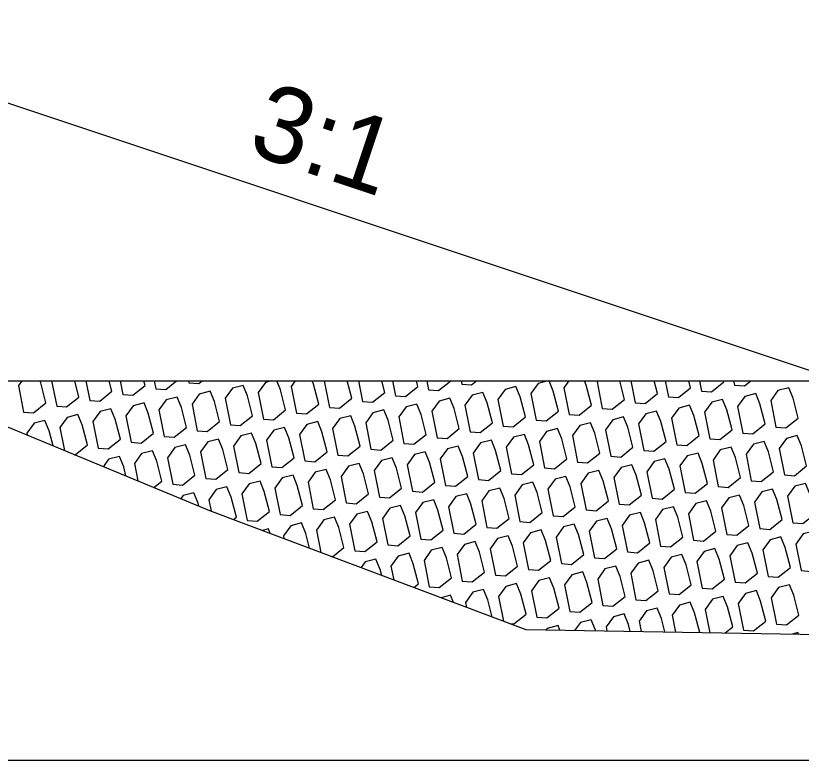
# Model space of a CAD drawing. Extents: x -26 to 203, y -10 to 20020.
# Drawn here: x 122.84 to 131.13, y 17500 to 17507.85 of the extents above; entities that cross this region are included whole.
import ezdxf

# ---------------------------------------------------------------- set-up
doc = ezdxf.new("R2010")
doc.units = 0
for name, color, linetype in [('Exist Cross Section Cell', 7, 'Continuous'), ('Exist XS Ground Line', 7, 'Continuous'), ('Old_Level_1', 7, 'Continuous'), ('Prop CMT Rip Rap Class II', 7, 'Continuous'), ('Prop CMT Slope Grass', 7, 'Continuous'), ('Prop XS Side Slope Text', 7, 'Continuous')]:
    doc.layers.add(name, color=color, linetype=linetype)

msp = doc.modelspace()

# ---------------------------------------------------------------- linework, layer by layer
at = {"layer": 'Exist Cross Section Cell'}
msp.add_line((100, 17500), (200, 17500), dxfattribs=at)
at = {"layer": 'Exist XS Ground Line'}
for p, q in [((122.4332, 17503.6477), (124.8872, 17502.6334)), ((124.8872, 17502.6334), (128.2219, 17501.3773)), ((128.2219, 17501.3773), (137.4014, 17501.2258))]:
    msp.add_line(p, q, dxfattribs=at)
at = {"layer": 'Old_Level_1'}
for p, q in [((123.2212, 17504), (123.2742, 17503.7332)), ((123.582, 17504), (123.6228, 17503.7947)), ((123.9428, 17504), (123.9713, 17503.8562)), ((124.3036, 17504), (124.3199, 17503.9176)), ((124.6644, 17504), (124.6685, 17503.9791)), ((126.0964, 17504), (126.1518, 17503.7209)), ((126.4572, 17504), (126.5004, 17503.7824)), ((126.818, 17504), (126.849, 17503.8438)), ((127.1788, 17504), (127.1976, 17503.9053)), ((127.5396, 17504), (127.5462, 17503.9668)), ((129.3324, 17504), (129.3781, 17503.77)), ((129.6932, 17504), (129.7267, 17503.8315)), ((130.054, 17504), (130.0753, 17503.893)), ((130.4148, 17504), (130.4238, 17503.9544))]:
    msp.add_line(p, q, dxfattribs=at)
for points in [[(122.9049, 17504), (122.8699, 17503.9518), (122.9256, 17503.6718)], [(122.9256, 17503.6718), (123.0308, 17503.6641), (123.1604, 17503.7673), (123.1059, 17503.9779), (123.0968, 17504)], [(123.2742, 17503.7332), (123.3794, 17503.7256), (123.509, 17503.8288), (123.4647, 17504)], [(123.6228, 17503.7947), (123.728, 17503.7871), (123.8576, 17503.8903), (123.8292, 17504)], [(123.9713, 17503.8562), (124.0766, 17503.8485), (124.2062, 17503.9517), (124.1937, 17504)], [(124.3199, 17503.9176), (124.4252, 17503.91), (124.5382, 17504)], [(124.6685, 17503.9791), (124.7738, 17503.9715), (124.8096, 17504)], [(125.106, 17503.5365), (125.2113, 17503.5289), (125.3408, 17503.6321), (125.2864, 17503.8426), (125.2412, 17503.9523), (125.1275, 17503.9229), (125.0504, 17503.8165), (125.106, 17503.5365)], [(125.5364, 17504), (125.4761, 17503.9844), (125.399, 17503.878), (125.4546, 17503.598)], [(125.4546, 17503.598), (125.5599, 17503.5903), (125.6894, 17503.6935), (125.635, 17503.9041), (125.5955, 17504)], [(125.7915, 17504), (125.7476, 17503.9394), (125.8032, 17503.6594)], [(125.8032, 17503.6594), (125.9085, 17503.6518), (126.038, 17503.755), (125.9836, 17503.9656), (125.9694, 17504)], [(126.1518, 17503.7209), (126.2571, 17503.7133), (126.3866, 17503.8165), (126.3392, 17504)], [(126.5004, 17503.7824), (126.6057, 17503.7747), (126.7352, 17503.8779), (126.7036, 17504)], [(126.849, 17503.8438), (126.9543, 17503.8362), (127.0838, 17503.9394), (127.0681, 17504)], [(127.1976, 17503.9053), (127.3029, 17503.8977), (127.4313, 17504)], [(127.5462, 17503.9668), (127.6515, 17503.9591), (127.7028, 17504)], [(128.4618, 17504), (128.3537, 17503.9721), (128.2767, 17503.8656), (128.3323, 17503.5856)], [(128.3323, 17503.5856), (128.4375, 17503.578), (128.5671, 17503.6812), (128.5126, 17503.8918), (128.4681, 17504)], [(128.678, 17504), (128.6253, 17503.9271), (128.6809, 17503.6471)], [(128.6809, 17503.6471), (128.7861, 17503.6395), (128.9157, 17503.7427), (128.8612, 17503.9532), (128.842, 17504)], [(128.9821, 17504), (128.9739, 17503.9886), (129.0295, 17503.7086)], [(129.0295, 17503.7086), (129.1347, 17503.7009), (129.2643, 17503.8041), (129.2136, 17504)], [(129.3781, 17503.77), (129.4833, 17503.7624), (129.6129, 17503.8656), (129.5781, 17504)], [(129.7267, 17503.8315), (129.8319, 17503.8239), (129.9615, 17503.9271), (129.9426, 17504)], [(130.0753, 17503.893), (130.1805, 17503.8853), (130.3101, 17503.9885), (130.3071, 17504)], [(130.4238, 17503.9544), (130.5291, 17503.9468), (130.5959, 17504)], [(124.7574, 17503.475), (124.8627, 17503.4674), (124.9922, 17503.5706), (124.9378, 17503.7812), (124.8926, 17503.8909), (124.7789, 17503.8615), (124.7018, 17503.755), (124.7574, 17503.475)], [(127.6351, 17503.4627), (127.7403, 17503.4551), (127.8699, 17503.5583), (127.8154, 17503.7688), (127.7703, 17503.8785), (127.6565, 17503.8491), (127.5795, 17503.7427), (127.6351, 17503.4627)], [(127.9837, 17503.5242), (128.0889, 17503.5165), (128.2185, 17503.6197), (128.164, 17503.8303), (128.1189, 17503.94), (128.0051, 17503.9106), (127.9281, 17503.8042), (127.9837, 17503.5242)], [(124.4088, 17503.4136), (124.5141, 17503.4059), (124.6436, 17503.5091), (124.5892, 17503.7197), (124.544, 17503.8294), (124.4303, 17503.8), (124.3532, 17503.6936), (124.4088, 17503.4136)], [(123.7116, 17503.2906), (123.8169, 17503.283), (123.9464, 17503.3862), (123.892, 17503.5968), (123.8468, 17503.7065), (123.7331, 17503.6771), (123.656, 17503.5706), (123.7116, 17503.2906)], [(124.0602, 17503.3521), (124.1655, 17503.3445), (124.295, 17503.4477), (124.2406, 17503.6582), (124.1954, 17503.7679), (124.0817, 17503.7385), (124.0046, 17503.6321), (124.0602, 17503.3521)], [(123.4634, 17503.2219), (123.4683, 17503.2215), (123.5978, 17503.3247), (123.5434, 17503.5353), (123.4982, 17503.645), (123.3845, 17503.6156), (123.3074, 17503.5092), (123.3556, 17503.2664)], [(123.2356, 17503.316), (123.1948, 17503.4738), (123.1497, 17503.5835), (123.0359, 17503.5541), (122.9588, 17503.4477), (122.9626, 17503.4289)], [(124.0054, 17502.9979), (123.9809, 17503.0927), (123.9357, 17503.2024), (123.822, 17503.173), (123.7666, 17503.0966)], [(124.2995, 17502.8763), (124.3839, 17502.9436), (124.3295, 17503.1542), (124.2843, 17503.2639), (124.1706, 17503.2345), (124.0935, 17503.128), (124.1295, 17502.9466)], [(125.1397, 17502.5383), (125.17, 17502.5625), (125.1155, 17502.773), (125.0704, 17502.8827), (124.9566, 17502.8533), (124.8796, 17502.7469), (124.9033, 17502.6273)], [(125.2838, 17502.5284), (125.389, 17502.5207), (125.5186, 17502.6239), (125.4641, 17502.8345), (125.419, 17502.9442), (125.3052, 17502.9148), (125.2282, 17502.8084), (125.2838, 17502.5284)], [(124.7752, 17502.6797), (124.7669, 17502.7116), (124.7218, 17502.8213), (124.608, 17502.7919), (124.584, 17502.7587)], [(126.4185, 17502.2087), (126.5237, 17502.2011), (126.6533, 17502.3043), (126.5988, 17502.5148), (126.5537, 17502.6245), (126.4399, 17502.5951), (126.3628, 17502.4887), (126.4185, 17502.2087)], [(126.1825, 17502.1455), (126.3047, 17502.2428), (126.2502, 17502.4534), (126.2051, 17502.5631), (126.0913, 17502.5337), (126.0142, 17502.4272), (126.0611, 17502.1912)], [(125.9419, 17502.2361), (125.9016, 17502.3919), (125.8565, 17502.5016), (125.7427, 17502.4722), (125.6656, 17502.3658), (125.6711, 17502.3381)], [(125.5276, 17502.3922), (125.5079, 17502.4401), (125.4441, 17502.4236)], [(127.2045, 17501.8276), (127.3098, 17501.8199), (127.4393, 17501.9231), (127.3849, 17502.1337), (127.3397, 17502.2434), (127.226, 17502.214), (127.1489, 17502.1076), (127.2045, 17501.8276)], [(126.7036, 17501.9492), (126.6877, 17502.0108), (126.6425, 17502.1205), (126.5288, 17502.0911), (126.4856, 17502.0313)], [(127.0411, 17501.8221), (127.0907, 17501.8617), (127.0363, 17502.0722), (126.9911, 17502.1819), (126.8774, 17502.1525), (126.8003, 17502.0461), (126.8289, 17501.902)], [(128.3392, 17501.5079), (128.4445, 17501.5003), (128.574, 17501.6035), (128.5196, 17501.814), (128.4744, 17501.9237), (128.3606, 17501.8943), (128.2836, 17501.7879), (128.3392, 17501.5079)], [(127.8691, 17501.5102), (127.8224, 17501.6911), (127.7772, 17501.8008), (127.6635, 17501.7714), (127.5864, 17501.665), (127.5968, 17501.6128)], [(128.0498, 17501.4421), (128.0959, 17501.4388), (128.2254, 17501.542), (128.171, 17501.7526), (128.1258, 17501.8623), (128.0121, 17501.8328), (127.935, 17501.7264), (127.9867, 17501.4659)], [(127.4594, 17501.6645), (127.4286, 17501.7393), (127.3291, 17501.7136)], [(130.3254, 17501.3426), (130.4059, 17501.4067), (130.3514, 17501.6173), (130.3063, 17501.727), (130.1925, 17501.6976), (130.1155, 17501.5912), (130.1643, 17501.3452)], [(130.0568, 17501.347), (130.0028, 17501.5558), (129.9577, 17501.6655), (129.8439, 17501.6361), (129.7669, 17501.5297), (129.8023, 17501.3512)], [(129.3247, 17501.3591), (129.3056, 17501.4329), (129.2605, 17501.5426), (129.1467, 17501.5132), (129.0697, 17501.4068), (129.0783, 17501.3632)], [(129.6908, 17501.3531), (129.6542, 17501.4944), (129.6091, 17501.6041), (129.4953, 17501.5746), (129.4183, 17501.4682), (129.4403, 17501.3572)], [(128.9587, 17501.3651), (128.957, 17501.3714), (128.9119, 17501.4811), (128.7981, 17501.4517), (128.7381, 17501.3688)], [(128.5832, 17501.3713), (128.5633, 17501.4197), (128.4495, 17501.3902), (128.4376, 17501.3737)], [(131.099, 17501.3298), (131.0923, 17501.3459), (131.0344, 17501.3309)]]:
    msp.add_lwpolyline(points, dxfattribs=at)
for points in [[(130.5127, 17503.4504), (130.618, 17503.4427), (130.7475, 17503.5459), (130.6931, 17503.7565), (130.6479, 17503.8662), (130.5342, 17503.8368), (130.4571, 17503.7304)], [(130.8613, 17503.5118), (130.9666, 17503.5042), (131.0961, 17503.6074), (131.0417, 17503.818), (130.9965, 17503.9277), (130.8828, 17503.8983), (130.8057, 17503.7918)], [(127.2865, 17503.4012), (127.3917, 17503.3936), (127.5213, 17503.4968), (127.4668, 17503.7074), (127.4217, 17503.8171), (127.3079, 17503.7877), (127.2309, 17503.6812)], [(130.1641, 17503.3889), (130.2694, 17503.3813), (130.3989, 17503.4845), (130.3445, 17503.695), (130.2993, 17503.8047), (130.1856, 17503.7753), (130.1085, 17503.6689)], [(126.5893, 17503.2783), (126.6946, 17503.2707), (126.8241, 17503.3739), (126.7696, 17503.5844), (126.7245, 17503.6941), (126.6107, 17503.6647), (126.5337, 17503.5583)], [(126.9379, 17503.3398), (127.0431, 17503.3321), (127.1727, 17503.4353), (127.1182, 17503.6459), (127.0731, 17503.7556), (126.9593, 17503.7262), (126.8823, 17503.6198)], [(129.8155, 17503.3274), (129.9208, 17503.3198), (130.0503, 17503.423), (129.9959, 17503.6336), (129.9507, 17503.7433), (129.837, 17503.7139), (129.7599, 17503.6074)], [(126.2407, 17503.2168), (126.346, 17503.2092), (126.4755, 17503.3124), (126.421, 17503.523), (126.3759, 17503.6327), (126.2621, 17503.6033), (126.1851, 17503.4968)], [(129.1183, 17503.2045), (129.2236, 17503.1969), (129.3531, 17503.3001), (129.2987, 17503.5106), (129.2536, 17503.6203), (129.1398, 17503.5909), (129.0627, 17503.4845)], [(129.4669, 17503.266), (129.5722, 17503.2583), (129.7017, 17503.3615), (129.6473, 17503.5721), (129.6022, 17503.6818), (129.4884, 17503.6524), (129.4113, 17503.546)], [(125.8921, 17503.1554), (125.9974, 17503.1477), (126.1269, 17503.2509), (126.0725, 17503.4615), (126.0273, 17503.5712), (125.9135, 17503.5418), (125.8365, 17503.4354)], [(128.7697, 17503.143), (128.875, 17503.1354), (129.0045, 17503.2386), (128.9501, 17503.4492), (128.905, 17503.5589), (128.7912, 17503.5295), (128.7141, 17503.423)], [(125.1949, 17503.0324), (125.3002, 17503.0248), (125.4297, 17503.128), (125.3753, 17503.3386), (125.3301, 17503.4483), (125.2164, 17503.4189), (125.1393, 17503.3124)], [(125.5435, 17503.0939), (125.6488, 17503.0863), (125.7783, 17503.1895), (125.7239, 17503.4), (125.6787, 17503.5097), (125.5649, 17503.4803), (125.4879, 17503.3739)], [(128.4212, 17503.0816), (128.5264, 17503.0739), (128.656, 17503.1771), (128.6015, 17503.3877), (128.5564, 17503.4974), (128.4426, 17503.468), (128.3655, 17503.3616)], [(124.8463, 17502.971), (124.9516, 17502.9633), (125.0811, 17503.0665), (125.0267, 17503.2771), (124.9815, 17503.3868), (124.8678, 17503.3574), (124.7907, 17503.251)], [(127.724, 17502.9586), (127.8292, 17502.951), (127.9588, 17503.0542), (127.9043, 17503.2648), (127.8592, 17503.3745), (127.7454, 17503.3451), (127.6683, 17503.2386)], [(128.0726, 17503.0201), (128.1778, 17503.0125), (128.3074, 17503.1157), (128.2529, 17503.3262), (128.2078, 17503.4359), (128.094, 17503.4065), (128.0169, 17503.3001)], [(130.6016, 17502.9463), (130.7069, 17502.9387), (130.8364, 17503.0419), (130.782, 17503.2524), (130.7368, 17503.3621), (130.6231, 17503.3327), (130.546, 17503.2263)], [(130.9502, 17503.0078), (131.0555, 17503.0001), (131.185, 17503.1033), (131.1306, 17503.3139), (131.0854, 17503.4236), (130.9717, 17503.3942), (130.8946, 17503.2878)], [(124.4977, 17502.9095), (124.603, 17502.9019), (124.7325, 17503.0051), (124.6781, 17503.2156), (124.6329, 17503.3253), (124.5192, 17503.2959), (124.4421, 17503.1895)], [(127.3754, 17502.8972), (127.4806, 17502.8895), (127.6102, 17502.9927), (127.5557, 17503.2033), (127.5106, 17503.313), (127.3968, 17503.2836), (127.3198, 17503.1772)], [(130.253, 17502.8848), (130.3583, 17502.8772), (130.4878, 17502.9804), (130.4334, 17503.191), (130.3882, 17503.3007), (130.2745, 17503.2713), (130.1974, 17503.1648)], [(127.0268, 17502.8357), (127.132, 17502.8281), (127.2616, 17502.9313), (127.2071, 17503.1418), (127.162, 17503.2515), (127.0482, 17503.2221), (126.9712, 17503.1157)], [(129.9044, 17502.8234), (130.0097, 17502.8157), (130.1392, 17502.9189), (130.0848, 17503.1295), (130.0396, 17503.2392), (129.9259, 17503.2098), (129.8488, 17503.1034)], [(126.3296, 17502.7128), (126.4348, 17502.7051), (126.5644, 17502.8083), (126.5099, 17503.0189), (126.4648, 17503.1286), (126.351, 17503.0992), (126.274, 17502.9928)], [(126.6782, 17502.7742), (126.7834, 17502.7666), (126.913, 17502.8698), (126.8585, 17503.0804), (126.8134, 17503.1901), (126.6996, 17503.1607), (126.6226, 17503.0542)], [(129.2072, 17502.7004), (129.3125, 17502.6928), (129.442, 17502.796), (129.3876, 17503.0066), (129.3424, 17503.1163), (129.2287, 17503.0869), (129.1516, 17502.9804)], [(129.5558, 17502.7619), (129.6611, 17502.7543), (129.7906, 17502.8575), (129.7362, 17503.068), (129.691, 17503.1777), (129.5773, 17503.1483), (129.5002, 17503.0419)], [(125.981, 17502.6513), (126.0862, 17502.6437), (126.2158, 17502.7469), (126.1613, 17502.9574), (126.1162, 17503.0671), (126.0024, 17503.0377), (125.9254, 17502.9313)], [(128.8586, 17502.639), (128.9639, 17502.6313), (129.0934, 17502.7345), (129.039, 17502.9451), (128.9938, 17503.0548), (128.8801, 17503.0254), (128.803, 17502.919)], [(125.6324, 17502.5898), (125.7376, 17502.5822), (125.8672, 17502.6854), (125.8127, 17502.896), (125.7676, 17503.0057), (125.6538, 17502.9763), (125.5768, 17502.8698)], [(128.51, 17502.5775), (128.6153, 17502.5699), (128.7448, 17502.6731), (128.6904, 17502.8836), (128.6452, 17502.9933), (128.5315, 17502.9639), (128.4544, 17502.8575)], [(127.8128, 17502.4546), (127.9181, 17502.4469), (128.0476, 17502.5501), (127.9932, 17502.7607), (127.9481, 17502.8704), (127.8343, 17502.841), (127.7572, 17502.7346)], [(128.1614, 17502.516), (128.2667, 17502.5084), (128.3962, 17502.6116), (128.3418, 17502.8222), (128.2966, 17502.9319), (128.1829, 17502.9025), (128.1058, 17502.796)], [(131.0391, 17502.5037), (131.1444, 17502.4961), (131.2739, 17502.5993), (131.2194, 17502.8098), (131.1743, 17502.9195), (131.0605, 17502.8901), (130.9835, 17502.7837)], [(127.4642, 17502.3931), (127.5695, 17502.3855), (127.699, 17502.4887), (127.6446, 17502.6992), (127.5995, 17502.8089), (127.4857, 17502.7795), (127.4086, 17502.6731)], [(130.3419, 17502.3808), (130.4472, 17502.3731), (130.5767, 17502.4763), (130.5223, 17502.6869), (130.4771, 17502.7966), (130.3633, 17502.7672), (130.2863, 17502.6608)], [(130.6905, 17502.4422), (130.7958, 17502.4346), (130.9253, 17502.5378), (130.8708, 17502.7484), (130.8257, 17502.8581), (130.7119, 17502.8287), (130.6349, 17502.7222)], [(127.1156, 17502.3316), (127.2209, 17502.324), (127.3504, 17502.4272), (127.296, 17502.6378), (127.2509, 17502.7475), (127.1371, 17502.7181), (127.06, 17502.6116)], [(129.9933, 17502.3193), (130.0986, 17502.3117), (130.2281, 17502.4149), (130.1737, 17502.6254), (130.1285, 17502.7351), (130.0148, 17502.7057), (129.9377, 17502.5993)], [(126.767, 17502.2702), (126.8723, 17502.2625), (127.0019, 17502.3657), (126.9474, 17502.5763), (126.9023, 17502.686), (126.7885, 17502.6566), (126.7114, 17502.5502)], [(129.6447, 17502.2578), (129.75, 17502.2502), (129.8795, 17502.3534), (129.8251, 17502.564), (129.7799, 17502.6737), (129.6662, 17502.6443), (129.5891, 17502.5378)], [(128.9475, 17502.1349), (129.0528, 17502.1273), (129.1823, 17502.2305), (129.1279, 17502.441), (129.0827, 17502.5507), (128.969, 17502.5213), (128.8919, 17502.4149)], [(129.2961, 17502.1964), (129.4014, 17502.1887), (129.5309, 17502.2919), (129.4765, 17502.5025), (129.4313, 17502.6122), (129.3176, 17502.5828), (129.2405, 17502.4764)], [(128.5989, 17502.0734), (128.7042, 17502.0658), (128.8337, 17502.169), (128.7793, 17502.3796), (128.7341, 17502.4893), (128.6204, 17502.4599), (128.5433, 17502.3534)], [(127.9017, 17501.9505), (128.007, 17501.9429), (128.1365, 17502.0461), (128.0821, 17502.2566), (128.0369, 17502.3663), (127.9232, 17502.3369), (127.8461, 17502.2305)], [(128.2503, 17502.012), (128.3556, 17502.0043), (128.4851, 17502.1075), (128.4307, 17502.3181), (128.3855, 17502.4278), (128.2718, 17502.3984), (128.1947, 17502.292)], [(131.128, 17501.9996), (131.2332, 17501.992), (131.3628, 17502.0952), (131.3083, 17502.3058), (131.2632, 17502.4155), (131.1494, 17502.3861), (131.0724, 17502.2796)], [(127.5531, 17501.889), (127.6584, 17501.8814), (127.7879, 17501.9846), (127.7335, 17502.1952), (127.6883, 17502.3049), (127.5746, 17502.2755), (127.4975, 17502.169)], [(130.4308, 17501.8767), (130.536, 17501.8691), (130.6656, 17501.9723), (130.6111, 17502.1828), (130.566, 17502.2925), (130.4522, 17502.2631), (130.3752, 17502.1567)], [(130.7794, 17501.9382), (130.8846, 17501.9305), (131.0142, 17502.0337), (130.9597, 17502.2443), (130.9146, 17502.354), (130.8008, 17502.3246), (130.7238, 17502.2182)], [(130.0822, 17501.8152), (130.1874, 17501.8076), (130.317, 17501.9108), (130.2625, 17502.1214), (130.2174, 17502.2311), (130.1036, 17502.2017), (130.0266, 17502.0952)], [(129.7336, 17501.7538), (129.8388, 17501.7461), (129.9684, 17501.8493), (129.9139, 17502.0599), (129.8688, 17502.1696), (129.755, 17502.1402), (129.678, 17502.0338)], [(129.0364, 17501.6308), (129.1417, 17501.6232), (129.2712, 17501.7264), (129.2167, 17501.937), (129.1716, 17502.0467), (129.0578, 17502.0173), (128.9808, 17501.9108)], [(129.385, 17501.6923), (129.4903, 17501.6847), (129.6198, 17501.7879), (129.5653, 17501.9984), (129.5202, 17502.1081), (129.4064, 17502.0787), (129.3294, 17501.9723)], [(128.6878, 17501.5694), (128.7931, 17501.5617), (128.9226, 17501.6649), (128.8682, 17501.8755), (128.823, 17501.9852), (128.7092, 17501.9558), (128.6322, 17501.8494)], [(130.5197, 17501.3726), (130.6249, 17501.365), (130.7545, 17501.4682), (130.7, 17501.6788), (130.6549, 17501.7885), (130.5411, 17501.759), (130.464, 17501.6526)], [(130.8683, 17501.4341), (130.9735, 17501.4265), (131.1031, 17501.5297), (131.0486, 17501.7402), (131.0035, 17501.8499), (130.8897, 17501.8205), (130.8126, 17501.7141)]]:
    msp.add_lwpolyline(points, close=True, dxfattribs=at)
at = {"layer": 'Prop CMT Rip Rap Class II'}
msp.add_lwpolyline([(121.4553, 17504), (133.5503, 17504), (137.71, 17501.2267)], dxfattribs=at)
at = {"layer": 'Prop CMT Slope Grass'}
msp.add_lwpolyline([(120, 17507.8497), (131.5503, 17504)], dxfattribs=at)

# ---------------------------------------------------------------- texts
at = {"layer": 'Prop XS Side Slope Text'}
msp.add_text('3:1', height=0.8, rotation=341.56677, dxfattribs=at).set_placement((125.2685, 17506.41))

doc.saveas('drawing.dxf')
